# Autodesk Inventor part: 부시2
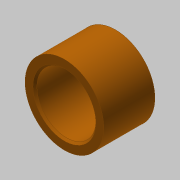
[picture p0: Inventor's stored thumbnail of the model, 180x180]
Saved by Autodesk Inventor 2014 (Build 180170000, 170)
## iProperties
Created: 2016-08
Part Number: 부시2
Material: 강철, 탄소
Document SubType Name: Modeling
Designer: mduedu
Density: 7.87 g/cm^3
Appearance: Orange
Author: mduedu
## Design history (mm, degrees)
sketch "스케치1"
  geometry: C1 r 7.5 at (0, 0); C2 r 10 at (0, 0); 1 further point
  constraints: 2 centre point, 2 coincident
  dimensions: "d0" = 15 diameter of C1; "d1" = 20 diameter of C2
extrude "돌출1" new body sketch "스케치1" stored distance "d2" = 13; taper "d3" = 0 deg
chamfer "모따기1" distance "d4" = 0.5; stored, may be unused: second distance "d5" = 2, angle "d6" = 45 deg
node "솔리드1"
